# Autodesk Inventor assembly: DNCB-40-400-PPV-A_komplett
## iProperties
Created: 2005-05
Part Number: DNCB-40-400-PPV-A_komplett
Document SubType Name: Assembly
Designer: tfa
Manufacturer: Standard
Standards Organization: Custom
Author: tfa
